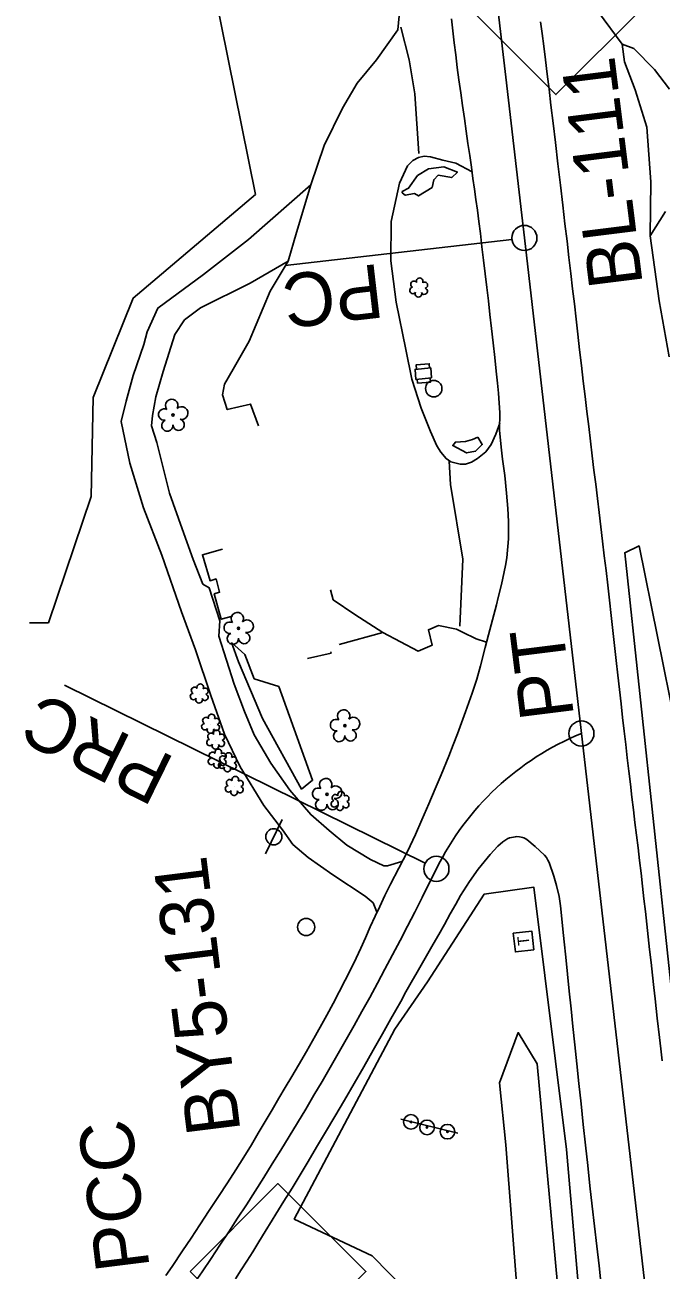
# Model space of a CAD drawing. Extents: x 476627 to 479509, y 495837 to 499842.
# Drawn here: x 477970.6 to 478160.5, y 497245.6 to 497616.9 of the extents above; entities that cross this region are included whole.
import ezdxf

# ---------------------------------------------------------------- set-up
doc = ezdxf.new("R2010")
doc.units = 0
for name, color, linetype in [('CTL Secondary Horizontal and Vertical CELL', 7, 'Continuous'), ('CTL Secondary Horizontal and Vertical Text', 7, 'Continuous'), ('Exist Building Metal Canopy', 7, 'Continuous'), ('Exist Horizontal Alignment', 7, 'Continuous'), ('Exist Other Culture Area Outline', 7, 'Continuous'), ('Exist Other Culture Sign', 7, 'Continuous'), ('Exist Other Culture Sign Post CELL', 7, 'Continuous'), ('Exist Other Culture Well CELL', 7, 'Continuous'), ('Exist Roads Change in Surface', 7, 'Continuous'), ('Exist Roads EOP', 7, 'Continuous'), ('Exist Roads EOP Other', 7, 'Continuous'), ('Exist Roads Soil', 7, 'Continuous'), ('Exist Utilities Other Pole CELL', 7, 'Continuous'), ('Exist Utilities Telephone Pedestal CELL', 7, 'Continuous'), ('Exist Utilities Telephone Pole CELL', 7, 'Continuous'), ('Exist Vegetation Hedge Row', 7, 'Continuous'), ('Exist Vegetation Shrub CELL', 7, 'Continuous'), ('Exist Vegetation Tree CELL', 7, 'Continuous'), ('Exist Vegetation Woods Line', 7, 'Continuous')]:
    doc.layers.add(name, color=color, linetype=linetype)

msp = doc.modelspace()

# ---------------------------------------------------------------- linework, layer by layer
at = {"layer": 'CTL Secondary Horizontal and Vertical CELL'}
for points in [[(478102.87, 497622.36), (478129.08, 497648.57), (478155.33, 497622.32), (478129.13, 497596.11)], [(478019.96, 497245.21), (478046.17, 497271.41), (478072.42, 497245.16), (478046.21, 497218.96)]]:
    msp.add_lwpolyline(points, close=True, dxfattribs=at)
at = {"layer": 'Exist Building Metal Canopy'}
msp.add_lwpolyline([(478092.02, 497511.64), (478087.35, 497511.2), (478087.07, 497514.18), (478091.75, 497514.62)], close=True, dxfattribs=at)
at = {"layer": 'Exist Horizontal Alignment'}
for p, q in [((478115.99, 497552.94), (478048.35, 497545.15)), ((478241.22, 496498.17), (478119.71, 497553.37)), ((478090.1, 497366.91), (477982.44, 497419.98))]:
    msp.add_line(p, q, dxfattribs=at)
for centre in [(478119.71, 497553.37), (478136.73, 497405.61), (478093.46, 497365.25)]:
    msp.add_circle(centre, 3.75, dxfattribs=at)
for centre, radius, start, end in [((394030.15, 487870.77), 84645.18, 6.5684633, 6.7177067), ((478168.37, 497328.32), 83.52, 112.2664, 153.7589), ((477193.06, 497809.1), 1003.86, 324.99436, 333.75894)]:
    msp.add_arc(centre, radius, start, end, dxfattribs=at)
at = {"layer": 'Exist Other Culture Area Outline'}
for points in [[(478083.23, 497567.22), (478085.14, 497568.18), (478087.82, 497572.04), (478091.08, 497574.02), (478095.69, 497574.6), (478099.73, 497572.99), (478098.03, 497571.35), (478094, 497572.05), (478092.65, 497570.73), (478092.23, 497568.45), (478088.06, 497565.91), (478086.88, 497566.62), (478084.14, 497566.09), (478083.25, 497566.86), (478083.23, 497567.22)], [(478091.4, 497514.59), (478091.31, 497515.84), (478087.43, 497515.57), (478087.52, 497514.22)], [(478087.73, 497511.24), (478087.81, 497510.1), (478091.7, 497510.38), (478091.62, 497511.6)], [(478105.85, 497493.95), (478107.12, 497491.74), (478105.12, 497489.79), (478102.44, 497489.27), (478098.33, 497491.46), (478099.13, 497492.49), (478102.17, 497492.72), (478104.23, 497493.29), (478105.85, 497493.95)], [(478032.55, 497440.64), (478029.22, 497439.65), (478027.13, 497447.26), (478028.74, 497447.71), (478027.71, 497451.71), (478025.9, 497451.17), (478023.63, 497458.89), (478029.61, 497460.6)], [(478077.51, 497435.73), (478064.42, 497432.19)], [(478061.99, 497429.98), (478062.04, 497429.57), (478055, 497427.99)]]:
    msp.add_lwpolyline(points, dxfattribs=at)
at = {"layer": 'Exist Other Culture Sign'}
msp.add_line((478099.82, 497286.46), (478082.88, 497290.56), dxfattribs=at)
at = {"layer": 'Exist Other Culture Sign Post CELL'}
for centre, radius in [((478085.85, 497289.78), 2.18), ((478085.85, 497289.78), 0.24), ((478090.66, 497288.15), 2.18), ((478090.66, 497288.15), 0.24), ((478096.76, 497286.87), 2.18), ((478096.76, 497286.87), 0.24)]:
    msp.add_circle(centre, radius, dxfattribs=at)
at = {"layer": 'Exist Other Culture Well CELL'}
msp.add_circle((478054.59, 497347.89), 2.56, dxfattribs=at)
at = {"layer": 'Exist Roads Change in Surface'}
for points in [[(478088.25, 497578.51), (478087.04, 497596.39), (478085.28, 497606.5), (478082.79, 497616.26)], [(478100.49, 497437.62), (478101.33, 497457.62), (478097.61, 497479.89), (478097.29, 497486.78)]]:
    msp.add_lwpolyline(points, dxfattribs=at)
at = {"layer": 'Exist Roads EOP'}
for points in [[(478012.69, 497244.02), (478014.57, 497246.71), (478017.72, 497251.38), (478020.21, 497255.11), (478022.88, 497259.13), (478025.68, 497263.34), (478028.43, 497267.51), (478031.07, 497271.58), (478033.6, 497275.51), (478036, 497279.3), (478038.22, 497282.91), (478040.28, 497286.38), (478042.35, 497289.88), (478044.44, 497293.43), (478046.44, 497296.82), (478048.36, 497300.06), (478050.28, 497303.3), (478052.26, 497306.67), (478054.65, 497310.79), (478057.4, 497315.56), (478059.77, 497319.79), (478060.77, 497321.63), (478062.62, 497325.11), (478064.43, 497328.57), (478066.2, 497332), (478067.92, 497335.35), (478069.51, 497338.58), (478070.9, 497341.63), (478072.25, 497344.68), (478073.69, 497347.93), (478075.14, 497351.13), (478076.54, 497354.05), (478078.1, 497357.29), (478079.78, 497360.65), (478082.25, 497365.42), (478084.85, 497370.41), (478087.21, 497375.53), (478089.12, 497379.83), (478091.22, 497384.63), (478093.13, 497389.15), (478094.86, 497393.31), (478097.12, 497398.83), (478098.47, 497402.23), (478099.73, 497405.49), (478100.96, 497408.76), (478102.14, 497412.02), (478104.11, 497417.64), (478105.48, 497421.78), (478106.61, 497425.8), (478108.04, 497431.23), (478109.03, 497435.01), (478110.21, 497439.54), (478111.36, 497444), (478111.91, 497446.15), (478112.87, 497450.01), (478114.12, 497455.67), (478114.5, 497457.99), (478115.01, 497463.63), (478114.96, 497468.8), (478114.77, 497472.67), (478114.41, 497477.31), (478113.83, 497482.51), (478113.22, 497487.37), (478112.78, 497491), (478112.31, 497496.1), (478112.35, 497501.21), (478111.95, 497507.09), (478111.68, 497510.06), (478111.32, 497513.6), (478110.88, 497517.72), (478110.4, 497522.08), (478109.92, 497526.34), (478109.44, 497530.51), (478108.96, 497534.58), (478108.48, 497538.62), (478108, 497542.65), (478107.52, 497546.7), (478107.04, 497550.74), (478106.57, 497554.66), (478106.12, 497558.31), (478105.68, 497561.69), (478105.26, 497564.82), (478104.83, 497567.88), (478104.37, 497571.09), (478103.9, 497574.45), (478103.39, 497577.95), (478102.87, 497581.56), (478102.34, 497585.25), (478101.8, 497589.01), (478101.25, 497592.85), (478100.7, 497596.69), (478100.18, 497600.49), (478099.69, 497604.23), (478099.21, 497607.93), (478098.76, 497611.57), (478098.33, 497615.17), (478097.92, 497618.72)], [(478124.55, 497617.86), (478124.99, 497614.35), (478125.47, 497610.52), (478125.97, 497606.48), (478126.5, 497602.23), (478127.06, 497597.77), (478127.65, 497592.95), (478128.3, 497587.63), (478128.99, 497581.8), (478129.73, 497575.45), (478130.48, 497569.07), (478131.18, 497563.1), (478131.83, 497557.55), (478132.44, 497552.43), (478133.01, 497547.57), (478133.57, 497542.82), (478134.1, 497538.19), (478134.62, 497533.68), (478135.14, 497529.19), (478135.67, 497524.64), (478136.2, 497520.04), (478136.75, 497515.37), (478137.3, 497510.71), (478137.84, 497506.12), (478138.37, 497501.61), (478138.91, 497497.16), (478139.43, 497492.78), (478139.96, 497488.45), (478140.48, 497484.17), (478140.99, 497479.94), (478141.51, 497475.72), (478142.02, 497471.48), (478142.53, 497467.22), (478143.05, 497462.94), (478143.56, 497458.62), (478144.08, 497454.25), (478144.6, 497449.81), (478145.11, 497445.32), (478145.63, 497440.81), (478146.14, 497436.32), (478146.64, 497431.84), (478147.14, 497427.39), (478147.62, 497422.99), (478148.1, 497418.68), (478148.57, 497414.48), (478149.03, 497410.37), (478149.49, 497406.33), (478149.94, 497402.32), (478150.4, 497398.35), (478150.87, 497394.42), (478151.33, 497390.52), (478151.79, 497386.65), (478152.25, 497382.82), (478152.71, 497379.03), (478153.17, 497375.25), (478153.62, 497371.47), (478154.07, 497367.69), (478154.52, 497363.91), (478154.96, 497360.12), (478155.4, 497356.33), (478155.83, 497352.55), (478156.26, 497348.77), (478156.68, 497344.98), (478157.1, 497341.18), (478157.51, 497337.36), (478157.93, 497333.54), (478158.33, 497329.86), (478158.71, 497326.49), (478159.38, 497320.7), (478160.06, 497314.93), (478160.43, 497311.6), (478160.83, 497307.97)], [(478142.67, 497240.96), (478141.99, 497246.84), (478141.32, 497252.75), (478140.64, 497258.7), (478139.96, 497264.68), (478139.28, 497270.69), (478138.61, 497276.75), (478137.94, 497282.85), (478137.27, 497288.99), (478136.62, 497295.18), (478135.98, 497301.27), (478135.37, 497307.15), (478134.78, 497312.8), (478134.21, 497318.24), (478133.66, 497323.53), (478133.12, 497328.73), (478132.6, 497333.85), (478132.09, 497338.88), (478131.62, 497343.47), (478131.23, 497347.28), (478130.91, 497350.3), (478130.46, 497354.26), (478130.05, 497356.98), (478129.26, 497360.32), (478128.48, 497363.05), (478127.11, 497367.1), (478126.74, 497367.88), (478126.28, 497368.62), (478125.72, 497369.33), (478122.94, 497371.94), (478120.41, 497373.99), (478119.98, 497374.26), (478119.59, 497374.47), (478119.18, 497374.63), (478118.74, 497374.74), (478118.27, 497374.81), (478117.41, 497374.86), (478117.05, 497374.84), (478115.29, 497374.5), (478115.02, 497374.41), (478114.76, 497374.29), (478113.25, 497373.29), (478111.8, 497371.97), (478109.54, 497369.53), (478105.91, 497365.12), (478103.3, 497361.44), (478100.68, 497357.26), (478099.2, 497354.74), (478097.57, 497351.86), (478095.84, 497348.69), (478094.16, 497345.68), (478092.53, 497342.83), (478089.68, 497337.9), (478087.7, 497334.48), (478085.95, 497331.4), (478084.35, 497328.53), (478082.79, 497325.72), (478079.89, 497320.53), (478077.35, 497316.03), (478074.62, 497311.22), (478071.75, 497306.23), (478068.87, 497301.24), (478065.99, 497296.3), (478063.14, 497291.44), (478060.32, 497286.69), (478057.67, 497282.21), (478055.19, 497278.01), (478052.77, 497273.97), (478050.37, 497270.04), (478047.96, 497266.13), (478045.55, 497262.28), (478044.43, 497260.47), (478042.38, 497257.15), (478040.49, 497254.07), (478038.64, 497251.06), (478036.88, 497248.22), (478035.23, 497245.64), (478033.52, 497243.02)]]:
    msp.add_lwpolyline(points, dxfattribs=at)
at = {"layer": 'Exist Roads EOP Other'}
for points in [[(478040.39, 497497.33), (478038, 497503.84), (478031.05, 497502.21), (478029.65, 497506.59), (478030.19, 497509.74), (478032.84, 497514.28), (478037.55, 497522.57), (478043.79, 497537.51), (478049.23, 497546.44), (478051.66, 497555.02), (478056.01, 497569.24), (478059.93, 497580.91), (478065.41, 497592.04), (478069.76, 497599.5), (478075.6, 497606.48), (478081.89, 497615.39), (478082.65, 497622.65), (478084.7, 497630.36), (478087.33, 497636.61), (478091.49, 497643.73), (478093.96, 497648.37)], [(478141.86, 497620.68), (478148.86, 497611.15), (478152.42, 497609.85), (478158.58, 497603.6), (478163.02, 497597.72)], [(478104.11, 497573.07), (478099.22, 497575.67), (478095.33, 497576.57), (478091.7, 497577.52), (478089.83, 497577.8), (478088.1, 497577.34), (478086.37, 497576.48), (478084.85, 497574.89), (478082.4, 497569.73), (478079.95, 497558.23), (478079.88, 497546.53), (478081.48, 497534.21), (478084.28, 497520.1), (478086.08, 497511.27), (478088.89, 497502.66), (478091.66, 497495.61), (478093.59, 497491.4), (478094.82, 497489.48), (478096.35, 497487.59), (478097.74, 497486.57), (478100.55, 497485.92), (478102.09, 497485.89), (478103.91, 497486.53), (478105.76, 497487.65), (478108.17, 497489.56), (478109.8, 497491.75), (478111.23, 497494.82), (478112.35, 497498.1)], [(478161.85, 497561.27), (478157.25, 497553.99), (478159.97, 497534.58), (478162.89, 497517.88)], [(478108.39, 497432.81), (478105.28, 497433.85), (478101.2, 497435.78), (478099.46, 497436.72), (478094.07, 497437.77), (478091.06, 497436.55), (478092.16, 497431.92), (478088.03, 497430.18), (478077.51, 497435.73), (478069.08, 497441.07), (478062.65, 497445.5), (478061.8, 497448.45)]]:
    msp.add_lwpolyline(points, dxfattribs=at)
at = {"layer": 'Exist Roads Soil'}
for points in [[(478157.25, 497553.99), (478157.43, 497570.07), (478156.24, 497586.44), (478152.82, 497597.52), (478149.57, 497605.9), (478148.86, 497611.15)], [(478075.79, 497352.16), (478074.55, 497355.1), (478072.19, 497357.11), (478062.49, 497363.44), (478055.18, 497368.61), (478050.63, 497372.54), (478047.52, 497376.88), (478041.95, 497384.11), (478034.93, 497395.7), (478030.23, 497405.4), (478026.14, 497416.89), (478021.52, 497430.54), (478017.33, 497441.88), (478011.5, 497458.75), (478006.06, 497472.86), (478001.91, 497486.25), (477999.38, 497498.68), (478000.84, 497504.67), (478002.93, 497512.33), (478006.1, 497521.61), (478007.16, 497525.33), (478010.32, 497532.47), (478023.96, 497542.5), (478037.37, 497552.93), (478056.01, 497569.24)], [(478049.23, 497546.44), (478037.9, 497539.86), (478023.03, 497532.57), (478018.23, 497528.94), (478015.43, 497524.57), (478011.88, 497513.59), (478009.71, 497506), (478008.72, 497500.47), (478008.38, 497497.36), (478009.97, 497492.42), (478013.84, 497477.25), (478017.54, 497466.62), (478020.87, 497457.52), (478023.7, 497450.18), (478025.65, 497449.07), (478028.85, 497439.22), (478028.55, 497434.62), (478033.09, 497420.29), (478036.15, 497412.13), (478039.11, 497405.18), (478044.08, 497396.71), (478049.66, 497388.7), (478055.96, 497381.42), (478061.42, 497376.66), (478066.69, 497372.29), (478073.78, 497368.03), (478077.76, 497366.14), (478078.82, 497366.1), (478083.16, 497367.43)]]:
    msp.add_lwpolyline(points, dxfattribs=at)
at = {"layer": 'Exist Utilities Other Pole CELL'}
msp.add_circle((478092.66, 497508.45), 2.46, dxfattribs=at)
at = {"layer": 'Exist Utilities Telephone Pedestal CELL'}
msp.add_line((478119.45, 497343.51), (478119.45, 497343.51), dxfattribs=at)
msp.add_lwpolyline([(478122.57, 497341.13), (478121.92, 497346.69), (478116.37, 497346.04), (478117.01, 497340.49), (478122.57, 497341.13)], dxfattribs=at)
at = {"layer": 'Exist Utilities Telephone Pole CELL'}
for p, q in [((478042.44, 497369.7), (478047.39, 497379.91)), ((478044.92, 497374.81), (478044.92, 497374.81))]:
    msp.add_line(p, q, dxfattribs=at)
msp.add_circle((478044.92, 497374.81), 2.41, dxfattribs=at)
at = {"layer": 'Exist Vegetation Hedge Row'}
for points in [[(478190.09, 497080.94), (478179.04, 497176.49), (478167.62, 497291.69), (478149.68, 497459.52), (478153.94, 497461.52), (478164.92, 497407.53), (478169.64, 497380.94), (478176.79, 497323.8), (478179.27, 497301.23), (478182, 497244.2), (478186.73, 497178.82), (478185.59, 497158.67), (478193.35, 497075.53), (478190.09, 497080.94)], [(478032.28, 497432.78), (478036.32, 497429.2), (478039.1, 497421.91), (478046.38, 497419.57), (478056.5, 497391.66), (478053.21, 497389.04), (478041.57, 497410.03), (478034.37, 497427), (478032.28, 497432.78)], [(478061.9, 497159.5), (478060.76, 497167.21), (478076.59, 497184.26), (478079.28, 497196.19), (478077.12, 497216.22), (478089.28, 497228.61), (478089.68, 497234.1), (478074.26, 497249.81), (478051.02, 497260.79), (478081, 497317.4), (478090.81, 497331.53), (478107.74, 497357.73), (478122.56, 497359.77), (478132.29, 497281.51), (478141.65, 497174.35)]]:
    msp.add_lwpolyline(points, dxfattribs=at)
at = {"layer": 'Exist Vegetation Shrub CELL'}
for p, q in [((478088.23, 497538.4), (478088.23, 497538.4)), ((478022.75, 497417.34), (478022.75, 497417.34)), ((478026.14, 497408.33), (478026.14, 497408.33)), ((478027.64, 497403.61), (478027.64, 497403.61)), ((478028.1, 497397.95), (478028.1, 497397.95)), ((478031.19, 497396.84), (478031.19, 497396.84)), ((478033.2, 497389.79), (478033.2, 497389.79)), ((478064.77, 497385.32), (478064.77, 497385.32))]:
    msp.add_line(p, q, dxfattribs=at)
for centre, radius, start, end in [((478088.46, 497540.45), 0.99, 334.8391, 200.4717), ((478086.43, 497537.7), 0.955, 95.1099, 327.9534), ((478086.75, 497539.53), 0.968, 35.8908, 245.4216), ((478088.11, 497536.72), 0.984, 151.2797, 21.387), ((478089.87, 497537.48), 0.937, 204.9913, 73.4601), ((478089.91, 497539.27), 0.929, 284.4567, 126.0861), ((478021.27, 497418.46), 0.968, 35.8908, 245.4216), ((478022.98, 497419.38), 0.99, 334.8391, 200.4717), ((478024.42, 497418.21), 0.929, 284.4567, 126.0861), ((478020.95, 497416.63), 0.955, 95.1099, 327.9534), ((478022.62, 497415.65), 0.984, 151.2797, 21.387), ((478024.39, 497416.41), 0.937, 204.9913, 73.4601), ((478026.36, 497410.37), 0.99, 334.8391, 200.4717), ((478024.33, 497407.63), 0.955, 95.1099, 327.9534), ((478024.65, 497409.46), 0.968, 35.8908, 245.4216), ((478026.01, 497406.65), 0.984, 151.2797, 21.387), ((478027.77, 497407.4), 0.937, 204.9913, 73.4601), ((478027.81, 497409.2), 0.929, 284.4567, 126.0861), ((478025.84, 497402.91), 0.955, 95.1099, 327.9534), ((478026.16, 497404.74), 0.968, 35.8908, 245.4216), ((478027.87, 497405.65), 0.99, 334.8391, 200.4717), ((478029.28, 497402.68), 0.937, 204.9913, 73.4601), ((478029.31, 497404.48), 0.929, 284.4567, 126.0861), ((478026.62, 497399.08), 0.968, 35.8908, 245.4216), ((478027.51, 497401.93), 0.984, 151.2797, 21.387), ((478028.33, 497399.99), 0.99, 334.8391, 200.4717), ((478029.77, 497398.82), 0.929, 284.4567, 126.0861), ((478031.42, 497398.88), 0.99, 334.8391, 200.4717), ((478026.3, 497397.24), 0.955, 95.1099, 327.9534), ((478027.97, 497396.26), 0.984, 151.2797, 21.387), ((478029.39, 497396.13), 0.955, 95.1099, 327.9534), ((478029.71, 497397.97), 0.968, 35.8908, 245.4216), ((478029.74, 497397.02), 0.937, 204.9913, 73.4601), ((478032.83, 497395.91), 0.937, 204.9913, 73.4601), ((478032.86, 497397.71), 0.929, 284.4567, 126.0861), ((478031.06, 497395.16), 0.984, 151.2797, 21.387), ((478033.43, 497391.83), 0.99, 334.8391, 200.4717), ((478031.4, 497389.09), 0.955, 95.1099, 327.9534), ((478031.72, 497390.92), 0.968, 35.8908, 245.4216), ((478033.07, 497388.11), 0.984, 151.2797, 21.387), ((478034.84, 497388.86), 0.937, 204.9913, 73.4601), ((478034.87, 497390.66), 0.929, 284.4567, 126.0861), ((478062.97, 497384.61), 0.955, 95.1099, 327.9534), ((478063.29, 497386.44), 0.968, 35.8908, 245.4216), ((478065, 497387.36), 0.99, 334.8391, 200.4717), ((478066.41, 497384.39), 0.937, 204.9913, 73.4601), ((478066.44, 497386.19), 0.929, 284.4567, 126.0861), ((478064.64, 497383.63), 0.984, 151.2797, 21.387)]:
    msp.add_arc(centre, radius, start, end, dxfattribs=at)
at = {"layer": 'Exist Vegetation Tree CELL'}
for p, q in [((478014.85, 497500.57), (478014.85, 497500.57)), ((478034.39, 497436.98), (478034.39, 497436.98)), ((478066.14, 497407.95), (478066.14, 497407.95)), ((478060.79, 497387.48), (478060.79, 497387.48))]:
    msp.add_line(p, q, dxfattribs=at)
for centre in [(478014.85, 497500.57), (478034.39, 497436.98), (478066.14, 497407.95), (478060.79, 497387.48)]:
    msp.add_circle(centre, 0.326, dxfattribs=at)
for centre, radius, start, end in [((478014.46, 497503.44), 1.86, 330.1651, 219.7134), ((478012.24, 497500.72), 1.73, 62.6636, 279.3457), ((478017.4, 497501.16), 1.9, 257.1011, 134.1999), ((478013.14, 497497.45), 1.69, 111.5671, 6.231), ((478016.52, 497497.67), 1.7, 181.2822, 74.56), ((478034.01, 497439.85), 1.86, 330.1651, 219.7134), ((478031.79, 497437.14), 1.73, 62.6636, 279.3457), ((478036.94, 497437.57), 1.9, 257.1011, 134.1999), ((478032.69, 497433.86), 1.69, 111.5671, 6.231), ((478036.07, 497434.08), 1.7, 181.2822, 74.56), ((478065.75, 497410.83), 1.86, 330.1651, 219.7134), ((478063.53, 497408.11), 1.73, 62.6636, 279.3457), ((478068.69, 497408.54), 1.9, 257.1011, 134.1999), ((478064.43, 497404.83), 1.69, 111.5671, 6.231), ((478067.81, 497405.05), 1.7, 181.2822, 74.56), ((478060.41, 497390.35), 1.86, 330.1651, 219.7134), ((478058.19, 497387.64), 1.73, 62.6636, 279.3457), ((478063.34, 497388.07), 1.9, 257.1011, 134.1999), ((478059.09, 497384.36), 1.69, 111.5671, 6.231), ((478062.47, 497384.58), 1.7, 181.2822, 74.56)]:
    msp.add_arc(centre, radius, start, end, dxfattribs=at)
at = {"layer": 'Exist Vegetation Woods Line'}
for points in [[(478027.96, 497668.21), (478027.09, 497627.45), (478039.5, 497566.35), (478002.92, 497535.46), (477991.01, 497505.83), (477990.37, 497476.29), (477977.65, 497438.65), (477971.98, 497438.61)], [(478121.98, 497180.8), (478120.53, 497202.22), (478117.63, 497237.89), (478114.13, 497282.93), (478112.24, 497301.41), (478117.88, 497316.42), (478123.49, 497307.06), (478133.32, 497201.56), (478134.86, 497185.26)]]:
    msp.add_lwpolyline(points, dxfattribs=at)

# ---------------------------------------------------------------- texts
at = {"layer": 'CTL Secondary Horizontal and Vertical Text'}
for s, p in [('BL-111', (478155.08, 497539.52)), ('BY5-131', (478035.02, 497286.97))]:
    msp.add_text(s, height=16, rotation=97.1248, dxfattribs=at).set_placement(p)
at = {"layer": 'Exist Horizontal Alignment'}
for s, rotation, p in [('PC', 186.5685, (478076.44, 497545.68)), ('PT', 97.1247, (478134.54, 497410.78)), ('PRC', 153.7589, (478015.93, 497398.16)), ('PCC', 97.1247, (478007.9, 497246.31))]:
    msp.add_text(s, height=16, rotation=rotation, dxfattribs=at).set_placement(p)
at = {"layer": 'Exist Utilities Telephone Pedestal CELL'}
msp.add_text('T', height=3.42, rotation=96.6217, dxfattribs=at).set_placement((478121.28, 497342.59))

doc.saveas('drawing.dxf')
